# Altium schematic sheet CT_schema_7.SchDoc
size 278 x 170 mm
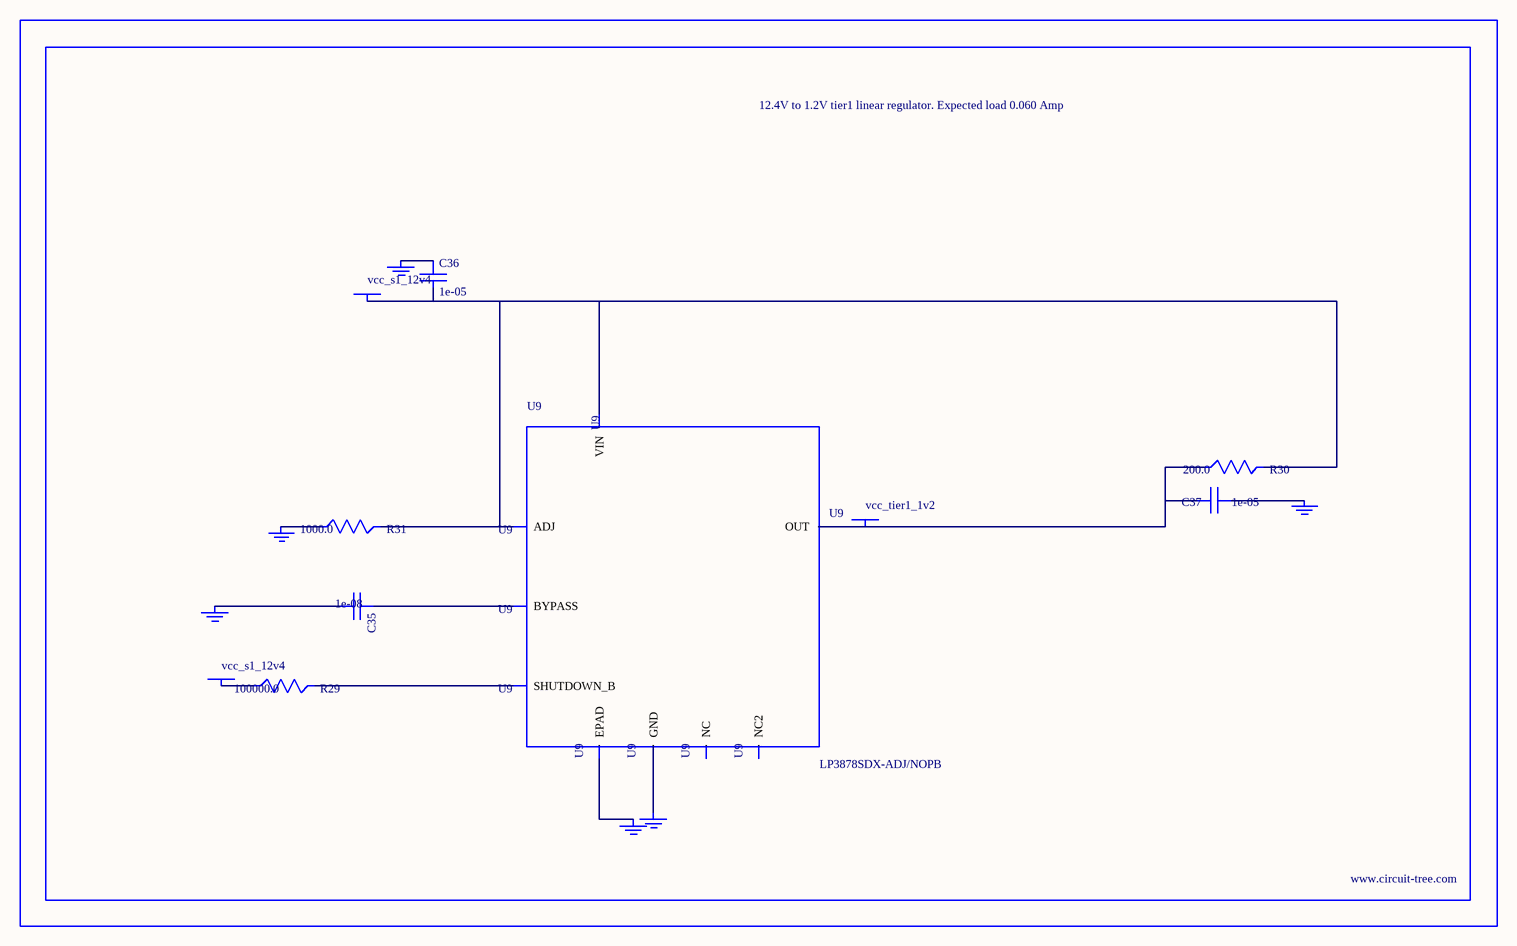
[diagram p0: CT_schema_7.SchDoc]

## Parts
BORDER6  (no value)
C35  1e-08  [C0402]
C36  1e-05  [C1210]
C37  1e-05  [C0805]
GND_INSTANCE_6_0  (no value)
GND_INSTANCE_6_1  (no value)
GND_INSTANCE_6_2  (no value)
GND_INSTANCE_6_3  (no value)
GND_INSTANCE_6_4  (no value)
GND_INSTANCE_6_5  (no value)
POWER_INSTANCE_6_0  vcc_s1_12v4
POWER_INSTANCE_6_1  vcc_s1_12v4
POWER_INSTANCE_6_2  vcc_tier1_1v2
R29  100000.0  [R0603]
R30  200.0  [R0603]
R31  1000.0  [R0603]
U9  LP3878SDX-ADJ/NOPB  [WSON-8]

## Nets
NetC35_1: C35.1 U9.1(BYPASS)
NetC35_2: C35.2 GND_INSTANCE_6_0.0(GND)
NetC36_1: C36.1 GND_INSTANCE_6_1.0(GND)
NetC36_2: C36.2 POWER_INSTANCE_6_0.0(PWR) R30.2 R31.2 U9.4(VIN) U9.6(ADJ)
NetC37_1: C37.1 GND_INSTANCE_6_2.0(GND)
NetC37_2: C37.2 POWER_INSTANCE_6_2.0(PWR) R30.1 U9.5(OUT)
NetGND_INSTANCE_6_3_0: GND_INSTANCE_6_3.0(GND) R31.1
NetGND_INSTANCE_6_4_0: GND_INSTANCE_6_4.0(GND) U9.PAD(EPAD)
NetGND_INSTANCE_6_5_0: GND_INSTANCE_6_5.0(GND) U9.3(GND)
NetPOWER_INSTANCE_6_1_0: POWER_INSTANCE_6_1.0(PWR) R29.1
NetR29_2: R29.2 U9.8(SHUTDOWN_B)

Not connected (* = marked no-connect by the designer): U9 2(NC) 7(NC2)

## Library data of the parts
BORDER6 = BORDER_PAGE6
C35 = C0402C103K3RAC
C36 = C1210C106K5PACTU
C37 = GRM219R60J106ME19D
GND_INSTANCE_6_0-GND_INSTANCE_6_5 = GND
POWER_INSTANCE_6_0-POWER_INSTANCE_6_2 = PWR
R29 = RC0603JR-07100KL
R30 = RC0603JR-07200RL
R31 = RC0603JR-071KL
